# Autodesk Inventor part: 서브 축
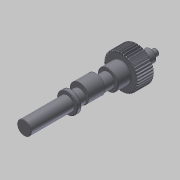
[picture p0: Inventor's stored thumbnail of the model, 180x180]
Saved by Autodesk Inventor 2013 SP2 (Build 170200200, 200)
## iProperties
Created: 2016-02
Part Number: 서브 축
Material: 강철, 연강
Document SubType Name: Modeling
Designer: mdu
Categories: <?xml version="1.0" encoding="UTF-16"?> <MemberInstance><Categories><FamilyTemplate><FamilyTemplateParameter ValueType="xs:double" Id="1" ObjectReferenceKey="da
Density: 7.86 g/cm^3
Mass: 506.173 g
Surface Area: 164.116 cm^2
Volume: 64.3986 cm^3
CustomPartVersion: 1
Author: mdu
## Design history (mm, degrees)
sketch "Sketch1"
  geometry: C1 r 21 at (0, 0)
  constraints: 1 centre point
  dimensions: "d0" = 42 diameter of C1 (= da_da)
extrude "Extrusion1" new body sketch "Sketch1" distance "d1" = 20 (= da_b); taper "d2" = 0 deg
workplane "Work Plane2"
feature "피치 지름" dims "d4" = 10, "d5" = 0
workplane "Work Plane8"
workplane "Work Plane9"
chamfer "모따기1" distance "d49" = 1; stored, may be unused: second distance "d50" = 2, angle "d51" = 45 deg
sketch "스케치3"
  geometry: C1 r 12.5 at (0, 0); 1 further point
  constraints: 1 centre point, 1 coincident
  dimensions: "d52" = 25 diameter of C1
extrude "돌출2" join sketch "스케치3" distance "d53" = 16; taper "d54" = 0 deg
sketch "스케치4"
  geometry: C1 r 8.5 at (0, 0); 1 further point
  constraints: 1 centre point, 1 coincident
  dimensions: "d55" = 17 diameter of C1
extrude "돌출3" join sketch "스케치4" distance "d56" = 103; taper "d57" = 0 deg
sketch "스케치5"
  geometry: C1 r 7.5 at (0, 0); 1 further point
  constraints: 1 centre point, 1 coincident
  dimensions: "d62" = 15 diameter of C1
extrude "돌출4" join sketch "스케치5" distance "d63" = 16; taper "d64" = 0 deg
sketch "스케치6"
  geometry: C1 r 4 at (0, 0); 1 further point
  constraints: 1 centre point, 1 coincident
  dimensions: "d65" = 8 diameter of C1
extrude "돌출5" join sketch "스케치6" distance "d66" = 7; taper "d67" = 0 deg
chamfer "모따기2" distance "d58" = 0.5; stored, may be unused: second distance "d59" = 2, angle "d60" = 45 deg
fillet "모깎기1" dims "d61" = 0.5
feature "스퍼 기어" dims "da_b" = 20, "da_d" = 40, "da_aw" = 31, "da_da" = 42, "da_df" = 37.5, "da_dw" = 40, angle "da_beta" = 0 deg, "da_lefttooth" = 0, "da_righttooth" = 0
node "작업 평면11"
sketch "스케치7"
  geometry: C1 r 8.5 at (0, 0) reference; C2 r 11.5 at (0, 3); 1 further point
  constraints: 1 centre point, 1 tangent, 1 vertical alignment
  dimensions: "d71" = 3 distance of C2.centre point (0, 0); "d72" = 23 diameter of C2 (derived)
extrude "돌출6" join sketch "스케치7" stored distance "d73" = 20; taper "d74" = 0 deg
node "작업 평면12"
sketch "스케치8"
  geometry: C1 r 12.5 at (0, 0) reference; 1 further point
extrude "돌출7" join sketch "스케치8" distance "d76" = 5; taper "d77" = 0 deg
chamfer "모따기3" distance "d78" = 0.5; stored, may be unused: second distance "d79" = 2, angle "d80" = 45 deg
body "Solid1"
sketch "Sketch2"
  geometry: C1 r 21 at (0, 0) reference; C2 r 20 at (0, 0)
  constraints: 1 centre point, 1 coincident
  dimensions: "d3" = 40 diameter of C2 (= da_dw)
body "Srf1"
other parameters: "d16" = 31 (= da_aw), "d17" = 0, "d34" = 4.5 deg (computed from da_z), "d39" = 0, "d41" = 0, "d43" = 31 (= da_aw), "d46" = 31 (= da_aw), "d47" = 0, "d48" = 0, "d68" = 25
